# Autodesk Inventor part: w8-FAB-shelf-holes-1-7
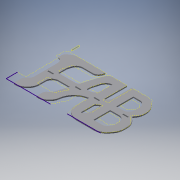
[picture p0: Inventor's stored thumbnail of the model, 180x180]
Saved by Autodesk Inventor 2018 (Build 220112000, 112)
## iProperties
Created: 2018-03
Part Number: w8-FAB-shelf-holes-1-7
Material: Generic
Document SubType Name: Modeling
Designer: katin
Density: 1 g/cm^3
Appearance: Default
Mass: 2767.77 g
Surface Area: 5780.22 cm^2
Volume: 2767.77 cm^3
Author: katin
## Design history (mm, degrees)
sketch "Sketch1"
  geometry: L1 (0, -103.188)-(-76.2, -103.188); L2 (-382.588, -407.987)-(-201.613, -407.987); L3 (-201.613, -407.987)-(-179.387, -330.2); L4 (-179.387, -330.2)-(-179.387, -303.315); L5 (-179.387, -303.315)-(-382.588, -303.315); L6 (-382.588, -303.315)-(-382.588, -330.2); L7 (-382.588, -330.2)-(-404.813, -407.987); L8 (-404.813, -407.987)-(-446.104, -500); L9 (-914.4, -410.18)-(-914.4, -330.2); L10 (-914.4, -330.2)-(-863.6, -279.4); L11 (-863.6, -279.4)-(-941.188, -201.812); L12 (-941.188, -100.013)-(-863.6, 0); L13 (-611.188, -500)-(-611.188, -274.637); L14 (-660.987, -274.638)-(-660.987, -501.799); L15 (-660.987, -203.2)-(-660.987, -104.775); L16 (-611.188, -104.775)-(-660.987, -104.775); L17 (-458.721, -302.879)-(-458.721, -330.2); L18 (-458.721, -330.2)-(-480.946, -407.987); L19 (-480.946, -407.987)-(-534.987, -407.987); L20 (-534.987, -407.987)-(-534.988, -302.879); L21 (-534.988, -302.879)-(-458.721, -302.879); L22 (-180.346, -201.117)-(-180.346, -104.775); L23 (-180.346, -104.775)-(-330, -104.775); L24 (-180.346, -201.117)-(-380.371, -201.117); L25 (-380.371, -201.117)-(-330, -104.775); L26 (-458.721, -201.117)-(-458.721, -104.775); L27 (-458.721, -201.117)-(-534.987, -201.117); L28 (-534.987, -201.117)-(-534.987, -104.775); L29 (-739.719, -407.987)-(-739.719, -306.388); L30 (-739.719, -407.987)-(-815.975, -407.987); L31 (-841.375, -354.012)-(-841.375, -381); L32 (-841.375, -381)-(-815.975, -407.987); L33 (-382.588, -407.987)-(-424.795, -502.08); L34 (-79.965, -502.08)-(-424.795, -502.08); L35 (-611.188, -104.775)-(-611.188, -203.2); L36 (-611.188, -500)-(-446.104, -500); L37 (0, -103.188)-(0, 0); L38 (-941.188, -201.812)-(-941.188, -100.013); L39 (0, -103.188)-(0, 0); L40 (0, 0)-(-406.4, 0); L41 (-406.4, 0)-(-458.721, -104.775); L42 (-534.987, -104.775)-(-558.8, 0); L43 (-611.188, -203.2)-(-660.987, -233.363); L44 (-660.987, -233.363)-(-660.987, -203.2); L45 (-558.8, 0)-(-863.6, 0); L46 (0, 0)-(-406.4, 0); L47 (-79.965, -502.08)-(-50.58, -485.849); L48 (-50.58, -485.849)-(-50.58, -407.987); L49 (-50.58, -407.987)-(-76.2, -407.987); L50 (-76.2, -407.987)-(-76.2, -103.188); L51 (-841.375, -354.012)-(-793.75, -306.388); L52 (-793.75, -306.388)-(-739.719, -306.388); L53 (-611.188, -274.637)-(-660.987, -274.638); L54 (-739.762, -201.612)-(-739.762, -103.187); L55 (-739.762, -103.187)-(-836.612, -103.188); L56 (-836.612, -103.188)-(-863.6, -138.112); L57 (-863.6, -138.112)-(-863.6, -176.213); L58 (-863.6, -176.213)-(-838.2, -201.612); L59 (-838.2, -201.612)-(-739.762, -201.612); L60 (-914.4, -410.18)-(-838.2, -501.799); L61 (-838.2, -501.799)-(-660.987, -501.799); L62 (0, 0)-(-406.4, 0); L63 (-558.8, 0)-(-863.6, 0)
  constraints: 126 end point, 13 perpendicular, 13 point on line, 10 vertical, 9 horizontal, 3 collinear, 1 parallel
sketch "Sketch2"
  geometry: L1 (0, 0)-(-940, 0); L2 (-940, 0)-(-940, -500); L3 (-940, -500)-(0, -500); L4 (0, -500)-(0, 0)
  constraints: 8 end point, 2 parallel, 1 horizontal, 1 perpendicular
  dimensions: "d10" = 940 distance of L3.end L2.end; "d11" = 500 distance of L2.end L1.end
extrude "Extrusion2" new body sketch "Sketch2" distance "d12" = 11; taper "d13" = 0 deg
sketch "Sketch3"
  geometry: L1 (0, 0)-(0, 500) reference; L2 (0, 408.758)-(113.674, 408.758); L3 (113.674, 408.758)-(113.674, 94.825); L4 (113.674, 94.825)-(0, 94.825); L5 (0, 94.825)-(0, 408.758); L6 (611.188, 500.062)-(650.182, 500.062); L7 (650.182, 500.062)-(650.182, 287.702); L8 (650.182, 287.702)-(611.188, 287.702); L9 (611.188, 287.702)-(611.188, 500.062); L10 (0, 500)-(129.919, 500); L11 (0, 500)-(940, 500) reference; L12 (129.919, 500)-(0, 408.758); L13 (0, 500)-(0, 408.758); L14 (739.775, 406.4)-(739.775, 307.975); L15 (739.775, 307.975)-(793.75, 307.975); L16 (793.75, 307.975)-(836.612, 350.838); L17 (836.612, 350.838)-(841.375, 355.6); L18 (841.375, 355.6)-(841.375, 381); L19 (841.375, 381)-(806.218, 418.355); L20 (806.218, 418.355)-(739.775, 418.355); L21 (739.775, 418.355)-(739.775, 406.4)
  constraints: 38 end point, 6 parallel, 4 perpendicular, 4 point on line, 2 horizontal, 1 collinear, 1 vertical
extrude "Extrusion3" cut sketch "Sketch3" distance "d14" = 150; taper "d15" = 0 deg
sketch "Sketch4"
  geometry: L1 (0, 500)-(940, 500) reference; L2 (839.788, 500)-(914.4, 411.163); L3 (914.4, 411.163)-(914.4, 310.193); L4 (914.4, 310.193)-(880.473, 275.82); L5 (880.473, 275.82)-(940, 217.064); L6 (940, 217.064)-(940, 500); L7 (940, 500)-(839.788, 500); L8 (940, 0)-(940, 500) reference; L9 (940, 99.14)-(940, 0); L10 (940, 0)-(863.6, 0); L11 (0, 0)-(940, 0) reference; L12 (940, 99.14)-(863.6, 0); L13 (728.744, 226.212)-(728.744, 72.721); L14 (728.744, 72.721)-(830.691, 72.721); L15 (830.691, 72.721)-(864.394, 116.456); L16 (864.394, 116.456)-(864.405, 192.017); L17 (864.405, 192.017)-(829.761, 226.212); L18 (829.761, 226.212)-(728.744, 226.212); L19 (649.575, 72.721)-(649.575, 226.081); L20 (649.575, 226.081)-(611.188, 202.869); L21 (611.188, 202.869)-(611.188, 72.721); L22 (611.188, 72.721)-(649.575, 72.721); L23 (727.378, 439.44)-(727.378, 283.141); L24 (727.378, 283.141)-(801.955, 283.141); L25 (801.955, 283.141)-(841.375, 322.561); L26 (841.375, 322.561)-(841.375, 403.65); L27 (841.375, 403.65)-(807.69, 439.44); L28 (807.69, 439.44)-(727.378, 439.44); L29 (534.987, 283.141)-(534.987, 439.44); L30 (534.987, 439.44)-(490.381, 439.44); L31 (490.381, 439.44)-(455.193, 321.307); L32 (455.193, 321.307)-(455.193, 283.141); L33 (455.193, 283.141)-(534.987, 283.141); L34 (534.987, 226.027)-(534.987, 72.721); L35 (534.987, 72.721)-(560.388, 0); L36 (560.388, 0)-(405.603, 0); L37 (455.193, 72.721)-(405.603, 0); L38 (455.193, 72.721)-(455.193, 226.027); L39 (455.193, 226.027)-(534.987, 226.027); L40 (250.031, 72.721)-(195.665, 72.721); L41 (195.665, 72.721)-(195.665, 226.027); L42 (195.665, 226.027)-(354.575, 226.027); L43 (354.575, 226.027)-(250.031, 72.721); L44 (195.665, 283.141)-(195.665, 362.436); L45 (195.665, 362.436)-(218.603, 439.44); L46 (218.603, 439.44)-(389.781, 439.44); L47 (389.781, 439.44)-(415.52, 500); L48 (415.52, 500)-(447.675, 500); L49 (611.188, 500)-(129.919, 500) reference; L50 (195.665, 283.141)-(380.412, 283.141); L51 (380.412, 283.141)-(380.412, 300.037); L52 (380.412, 300.037)-(421.936, 439.44); L53 (421.936, 439.44)-(447.675, 500); L54 (415.52, 500)-(447.675, 500); 1 further point
  constraints: 100 end point, 28 point on line, 12 perpendicular, 11 parallel, 3 vertical, 2 collinear
extrude "Extrusion4" cut sketch "Sketch4" distance "d16" = 150; taper "d17" = 0 deg
fillet "Fillet1" dims "d18" = 50
fillet "Fillet2" dims "d19" = 50
fillet "Fillet3" dims "d20" = 50
fillet "Fillet4" dims "d21" = 60
fillet "Fillet7" dims "d24" = 30
fillet "Fillet8" dims "d25" = 50
fillet "Fillet9" dims "d26" = 50
fillet "Fillet10" dims "d27" = 50
fillet "Fillet13" dims "d30" = 40
fillet "Fillet14" dims "d31" = 120
fillet "Fillet15" dims "d32" = 120
fillet "Fillet16" dims "d33" = 120
fillet "Fillet17" dims "d34" = 50
fillet "Fillet18" dims "d35" = 50
fillet "Fillet19" dims "d36" = 170
fillet "Fillet20" dims "d37" = 65
fillet "Fillet21" dims "d38" = 50
fillet "Fillet22" dims "d39" = 5
fillet "Fillet25" dims "d42" = 25
fillet "Fillet26" dims "d43" = 50
fillet "Fillet27" dims "d44" = 90
sketch "Sketch5"
  geometry: L1 (195.665, 72.721)-(195.665, 0); L2 (195.665, 0)-(278.632, 0); L3 (0, 0)-(285.193, 0) reference; L4 (278.632, 80.606)-(278.632, 0); L5 (278.632, 80.606)-(278.632, 104.775); L6 (223.608, 72.721)-(195.665, 72.721) reference; L7 (278.632, 104.775)-(195.665, 72.721)
  constraints: 10 end point, 2 vertical, 1 perpendicular, 1 point on line
extrude "Extrusion5" cut sketch "Sketch5" distance "d45" = 150; taper "d46" = 0 deg
sketch "Sketch6"
  geometry: L1 (463.037, 222.547)-(398.463, 127.297); L2 (398.463, 127.297)-(398.463, 22.263); L3 (455.193, 283.141)-(455.193, 311.832) reference; L4 (398.463, 22.263)-(534.988, 22.263); L5 (534.987, 226.027)-(534.987, 72.721) reference; L6 (534.988, 22.263)-(534.987, 226.027); L7 (534.987, 226.027)-(463.037, 222.547); 2 further points
  constraints: 10 end point, 2 perpendicular, 1 parallel
extrude "Extrusion6" cut sketch "Sketch6" distance "d48" = 150; taper "d49" = 0 deg
fillet "Fillet29" dims "d50" = 100
fillet "Fillet30" dims "d51" = 40
sketch "Sketch7"
  geometry: L1 (242.804, 83.41)-(242.804, 226.022); L2 (242.804, 226.022)-(357.713, 226.022); L3 (306.387, 83.41)-(242.804, 83.41); L4 (357.713, 226.022)-(313.861, 83.41); L5 (313.861, 83.41)-(242.804, 83.41); 1 further point
  constraints: 10 end point, 1 horizontal, 1 parallel, 1 perpendicular, 1 vertical
extrude "Extrusion7" cut sketch "Sketch7" distance "d52" = 150; taper "d53" = 0 deg
fillet "Fillet31" dims "d54" = 40
sketch "Sketch8"
  geometry: L1 (505.193, 226.027)-(534.987, 226.027) reference; L2 (534.987, 226.027)-(534.987, 72.721) reference; L3 (534.987, 127.541)-(534.987, 226.027); L4 (403.342, 127.541)-(534.987, 127.541); L5 (534.987, 226.027)-(435.488, 226.027); L6 (435.488, 226.027)-(403.342, 127.541); A1 r 100 centre (498.406, 96.512) between (415.634, 152.627) and (398.434, 98.891) reference; A2 r 100 centre (498.406, 96.512) between (415.634, 152.627) and (398.434, 98.891) reference; 2 further points
  constraints: 8 end point, 2 horizontal, 1 point on circle, 1 point on line, 1 tangent, 1 vertical
extrude "Extrusion8" cut sketch "Sketch8" distance "d55" = 150; taper "d56" = 0 deg
fillet "Fillet32" dims "d57" = 160
sketch "Sketch9"
  geometry: L1 (841.375, 322.561)-(801.955, 283.141) reference; L2 (841.375, 322.561)-(841.375, 298.749); L3 (841.375, 298.749)-(842.323, 283.141); L4 (842.323, 283.141)-(801.955, 283.141); 1 further point
  constraints: 6 end point, 1 perpendicular, 1 vertical
extrude "Extrusion9" cut sketch "Sketch9" distance "d58" = 150; taper "d59" = 0 deg
fillet "Fillet33" dims "d60" = 50
fillet "Fillet34" dims "d61" = 110
fillet "Fillet43" dims "d70" = 50
fillet "Fillet44" dims "d71" = 5
fillet "Fillet45" dims "d72" = 40
sketch "Sketch10"
  geometry: L1 (-1.587, 508)-(69.85, 508); L2 (69.85, 508)-(69.85, -22.225); L3 (69.85, -22.225)-(-1.587, -22.225); L4 (-1.587, -22.225)-(-1.587, 508); 1 further point
  constraints: 8 end point, 2 parallel, 1 horizontal, 1 perpendicular
extrude "Extrusion10" cut sketch "Sketch10" distance "d73" = 150; taper "d74" = 0 deg
fillet "Fillet46" dims "d75" = 40
fillet "Fillet47" dims "d76" = 5
fillet "Fillet48" dims "d77" = 5
fillet "Fillet49" dims "d78" = 5
sketch "Sketch16"
  geometry: L1 (131.762, 258.023)-(181.762, 258.023); L2 (181.762, 258.023)-(181.762, 247.023); L3 (181.762, 247.023)-(131.762, 247.023); L4 (131.762, 247.023)-(131.762, 258.023); L5 (382.587, 258.023)-(432.587, 258.023); L6 (432.587, 258.023)-(432.587, 247.023); L7 (432.587, 247.023)-(382.587, 247.023); L8 (382.587, 247.023)-(382.587, 258.023); L9 (554.038, 258.023)-(604.038, 258.023); L10 (604.038, 258.023)-(604.038, 247.023); L11 (604.038, 247.023)-(554.038, 247.023); L12 (554.038, 247.023)-(554.038, 258.023); L13 (817.562, 258.023)-(867.562, 258.023); L14 (867.562, 258.023)-(867.562, 247.023); L15 (867.562, 247.023)-(817.562, 247.023); L16 (817.562, 247.023)-(817.562, 258.023); 1 further point
  constraints: 32 end point, 8 parallel, 4 horizontal, 4 perpendicular, 2 point on line
  dimensions: "d106" = 50 distance of L2.end L3.end; "d107" = 11 distance of L1.end L2.end; "d108" = 50 distance of L6.end L7.end; "d109" = 11 distance of L5.end L6.end; "d110" = 50 distance of L10.end L11.end; "d111" = 11 distance of L9.end L10.end; "d112" = 50 distance of L14.end L15.end; "d113" = 11 distance of L13.end L14.end
extrude "Extrusion15" cut sketch "Sketch16" distance "d114" = 110; taper "d115" = 0 deg
workplane "Work Plane1"
body "Solid2"
